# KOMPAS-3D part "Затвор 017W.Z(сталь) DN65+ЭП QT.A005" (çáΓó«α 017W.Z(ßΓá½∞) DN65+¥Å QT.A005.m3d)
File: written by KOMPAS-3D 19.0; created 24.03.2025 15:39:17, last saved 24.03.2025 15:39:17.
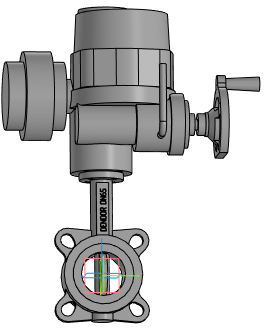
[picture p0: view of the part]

Document properties: Полное имя файла: Затвор 017W.Z(сталь) DN65+ЭП QT.A005.a3d

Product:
- Part/product: Затвор 017W.Z(сталь) DN65+ЭП QT.A005
    Масса: 39.7416

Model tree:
1. Операция без истории:1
